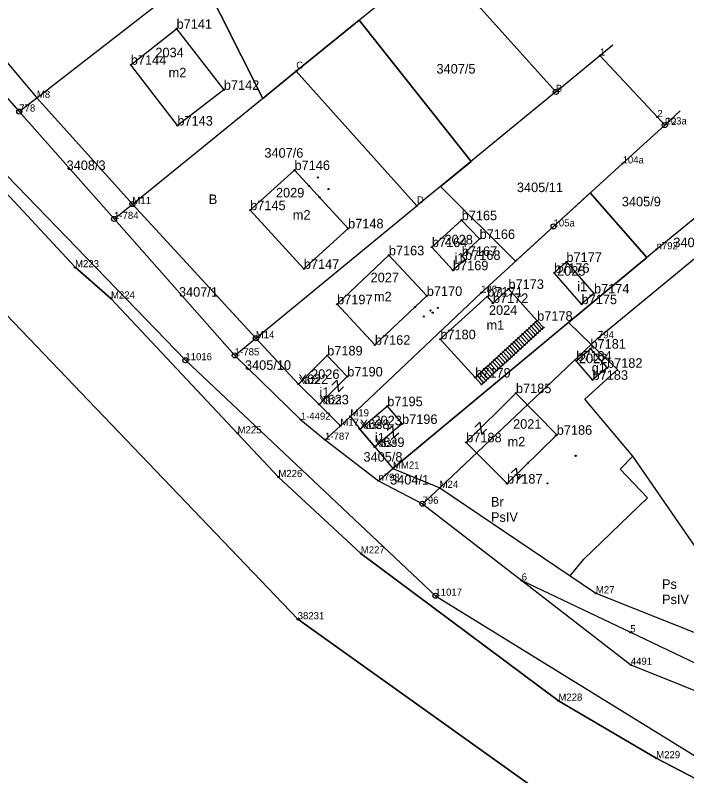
# Model space of a CAD drawing. Extents: x 7492083 to 7492670, y 5466693 to 5467065.
# Drawn here: x 7492234.2 to 7492339.8, y 5466813.8 to 5466933.4 of the extents above; entities that cross this region are included whole.
import ezdxf

# ---------------------------------------------------------------- set-up
doc = ezdxf.new("R2010")
doc.units = 0
for name, color, linetype in [('202-punkt graniczny', 7, 'Continuous'), ('202-punkt graniczny-Atr103', 7, 'Continuous'), ('203-punkt graniczny', 7, 'Continuous'), ('203-punkt graniczny-Atr103', 7, 'Continuous'), ('209-oznaczenie konturu klasyfikacyjnego', 7, 'Continuous'), ('210-oznaczenie konturu użytku gruntowego', 7, 'Continuous'), ('211-numer działki ewidencyjnej', 7, 'Continuous'), ('217-kontur klasyfikacyjny', 7, 'Continuous'), ('218-kontur użytku gruntowego', 7, 'Continuous'), ('219-działka ewidencyjna', 7, 'Continuous'), ('312-budynek ewidencyjny', 7, 'Continuous'), ('312-oznaczenie budynku ewidencyjnego', 7, 'Continuous'), ('312-oznaczenie budynku ewidencyjnego-Atr117', 7, 'Continuous'), ('352-schody', 7, 'Continuous'), ('991-Przehaczenie', 7, 'Continuous'), ('Punkt budynku', 7, 'Continuous'), ('Punkt budynku-Atr103', 7, 'Continuous')]:
    doc.layers.add(name, color=color, linetype=linetype)

# ---------------------------------------------------------------- blocks, each defined once
blk = doc.blocks.new('202')
blk.add_circle((0, 0), 0.4)
blk = doc.blocks.new('203')
blk.add_circle((0, 0), 0.09)
blk = doc.blocks.new('PUNKTBUD')
blk.add_circle((0, 0), 0.09)
blk = doc.blocks.new('991')
for p, q in [((-0.55, 0.75), (0.55, 0.75)), ((0.55, 0.75), (-0.55, -0.75)), ((-0.55, -0.75), (0.55, -0.75))]:
    blk.add_line(p, q)

msp = doc.modelspace()

# ---------------------------------------------------------------- linework, layer by layer
at = {"layer": '217-kontur klasyfikacyjny'}
for points in [[(7492263.09, 5466940.24), (7492273.09, 5466920.33)], [(7492278.38, 5466924.61), (7492288.26, 5466932.63)], [(7492288.26, 5466932.63), (7492305.89, 5466910.43)], [(7492273.09, 5466920.33), (7492278.38, 5466924.61)], [(7492305.89, 5466910.43), (7492301.07, 5466906.47)], [(7492301.07, 5466906.47), (7492312.89, 5466894.73)], [(7492318.86, 5466900.19), (7492324.64, 5466905.47)], [(7492324.64, 5466905.47), (7492333.55, 5466895.33)], [(7492312.89, 5466894.73), (7492318.86, 5466900.19)], [(7492333.55, 5466895.33), (7492321.19, 5466885.06)], [(7492321.19, 5466885.06), (7492293.59, 5466862.1)], [(7492324.8, 5466881.61), (7492321.19, 5466885.06)], [(7492328.91, 5466877.68), (7492324.8, 5466881.61)], [(7492323.78, 5466873.04), (7492328.91, 5466877.68)], [(7492331.33, 5466864.06), (7492323.78, 5466873.04)], [(7492329.32, 5466862.02), (7492331.33, 5466864.06)], [(7492341.15, 5466849.84), (7492331.33, 5466864.06)], [(7492293.59, 5466862.1), (7492300.94, 5466859.08)], [(7492333.65, 5466857.49), (7492329.32, 5466862.02)], [(7492300.94, 5466859.08), (7492321.46, 5466845.24)], [(7492323.63, 5466847.88), (7492333.65, 5466857.49)], [(7492321.46, 5466845.24), (7492323.63, 5466847.88)], [(7492321.46, 5466845.24), (7492325.52, 5466842.5)], [(7492325.52, 5466842.5), (7492392.56, 5466815.84)]]:
    msp.add_lwpolyline(points, dxfattribs=at)
at = {"layer": '218-kontur użytku gruntowego'}
for points in [[(7492273.09, 5466920.33), (7492263.09, 5466940.24)], [(7492223.67, 5466936.92), (7492237.56, 5466920.41)], [(7492288.26, 5466932.63), (7492278.38, 5466924.61)], [(7492305.89, 5466910.43), (7492288.26, 5466932.63)], [(7492278.38, 5466924.61), (7492273.09, 5466920.33)], [(7492237.56, 5466920.41), (7492252.59, 5466903.71)], [(7492243.57, 5466893.77), (7492219.52, 5466919.65)], [(7492278.6, 5466838.41), (7492203.36, 5466916.98)], [(7492301.07, 5466906.47), (7492305.89, 5466910.43)], [(7492312.89, 5466894.73), (7492301.07, 5466906.47)], [(7492324.64, 5466905.47), (7492318.86, 5466900.19)], [(7492333.55, 5466895.33), (7492324.64, 5466905.47)], [(7492252.59, 5466903.71), (7492272, 5466882.61)], [(7492318.86, 5466900.19), (7492312.89, 5466894.73)], [(7492321.19, 5466885.06), (7492333.55, 5466895.33)], [(7492249.22, 5466888.85), (7492243.57, 5466893.77)], [(7492269.15, 5466867.65), (7492249.22, 5466888.85)], [(7492321.19, 5466885.06), (7492293.59, 5466862.1)], [(7492324.8, 5466881.61), (7492321.19, 5466885.06)], [(7492272, 5466882.61), (7492278.71, 5466875.41)], [(7492328.91, 5466877.68), (7492324.8, 5466881.61)], [(7492323.78, 5466873.04), (7492328.91, 5466877.68)], [(7492278.71, 5466875.41), (7492281.96, 5466872.21)], [(7492331.33, 5466864.06), (7492323.78, 5466873.04)], [(7492281.96, 5466872.21), (7492285.31, 5466868.86)], [(7492285.31, 5466868.86), (7492286.89, 5466870.32)], [(7492286.89, 5466870.32), (7492288.36, 5466868.33)], [(7492275.56, 5466860.78), (7492269.15, 5466867.65)], [(7492288.36, 5466868.33), (7492290.72, 5466865.51)], [(7492290.72, 5466865.51), (7492293.59, 5466862.1)], [(7492329.32, 5466862.02), (7492331.33, 5466864.06)], [(7492341.15, 5466849.84), (7492331.33, 5466864.06)], [(7492293.59, 5466862.1), (7492300.94, 5466859.08)], [(7492333.65, 5466857.49), (7492329.32, 5466862.02)], [(7492288.53, 5466848.76), (7492275.56, 5466860.78)], [(7492300.94, 5466859.08), (7492321.46, 5466845.24)], [(7492323.63, 5466847.88), (7492333.65, 5466857.49)], [(7492319.62, 5466825.61), (7492288.53, 5466848.76)], [(7492321.46, 5466845.24), (7492323.63, 5466847.88)], [(7492321.46, 5466845.24), (7492325.52, 5466842.5)], [(7492325.52, 5466842.5), (7492392.56, 5466815.84)], [(7492330.31, 5466801.52), (7492278.6, 5466838.41)], [(7492335.01, 5466816.56), (7492319.62, 5466825.61)], [(7492351.02, 5466808.26), (7492335.01, 5466816.56)]]:
    msp.add_lwpolyline(points, dxfattribs=at)
at = {"layer": '219-działka ewidencyjna'}
for points in [[(7492237.56, 5466920.41), (7492278.95, 5466952.56)], [(7492198.51, 5466943.63), (7492260.93, 5466879.15)], [(7492300.32, 5466942.4), (7492278.38, 5466924.61)], [(7492300.32, 5466942.4), (7492319.2, 5466921.35)], [(7492223.67, 5466936.92), (7492237.56, 5466920.41)], [(7492220.55, 5466934.37), (7492234.8, 5466918.26)], [(7492326.15, 5466927.06), (7492328.2, 5466928.74)], [(7492319.2, 5466921.35), (7492326.15, 5466927.06)], [(7492326.15, 5466927.06), (7492335.19, 5466917.39)], [(7492252.59, 5466903.71), (7492278.38, 5466924.61)], [(7492278.38, 5466924.61), (7492297.36, 5466903.43)], [(7492319.2, 5466921.35), (7492297.36, 5466903.43)], [(7492234.8, 5466918.26), (7492237.56, 5466920.41)], [(7492237.56, 5466920.41), (7492252.59, 5466903.71)], [(7492219.52, 5466919.65), (7492243.57, 5466893.77)], [(7492234.8, 5466918.26), (7492249.71, 5466901.37)], [(7492336.47, 5466916.23), (7492338.8, 5466918.35)], [(7492203.36, 5466916.98), (7492278.6, 5466838.41)], [(7492335.19, 5466917.39), (7492336.36, 5466916.13)], [(7492329.72, 5466910.1), (7492336.36, 5466916.13)], [(7492336.36, 5466916.13), (7492336.47, 5466916.23)], [(7492318.86, 5466900.19), (7492329.72, 5466910.1)], [(7492335.07, 5466896.6), (7492349.18, 5466908.17)], [(7492325.85, 5466882.61), (7492352.68, 5466904.74)], [(7492249.71, 5466901.37), (7492252.59, 5466903.71)], [(7492252.59, 5466903.71), (7492272, 5466882.61)], [(7492272, 5466882.61), (7492297.36, 5466903.43)], [(7492249.71, 5466901.37), (7492268.71, 5466879.92)], [(7492307.46, 5466889.77), (7492318.86, 5466900.19)], [(7492293.59, 5466862.1), (7492335.07, 5466896.6)], [(7492243.57, 5466893.77), (7492249.22, 5466888.85)], [(7492286.89, 5466870.32), (7492307.46, 5466889.77)], [(7492249.22, 5466888.85), (7492269.15, 5466867.65)], [(7492268.71, 5466879.92), (7492272, 5466882.61)], [(7492272, 5466882.61), (7492278.71, 5466875.41)], [(7492300.94, 5466859.08), (7492325.85, 5466882.61)], [(7492268.71, 5466879.92), (7492279.09, 5466869.8)], [(7492260.93, 5466879.15), (7492300.27, 5466842.12)], [(7492278.71, 5466875.41), (7492281.96, 5466872.21)], [(7492281.96, 5466872.21), (7492285.31, 5466868.86)], [(7492285.31, 5466868.86), (7492286.89, 5466870.32)], [(7492286.89, 5466870.32), (7492288.36, 5466868.33)], [(7492279.09, 5466869.8), (7492282.91, 5466866.65)], [(7492282.91, 5466866.65), (7492285.31, 5466868.86)], [(7492269.15, 5466867.65), (7492275.56, 5466860.78)], [(7492288.36, 5466868.33), (7492290.72, 5466865.51)], [(7492282.91, 5466866.65), (7492291.31, 5466860.2)], [(7492290.72, 5466865.51), (7492293.59, 5466862.1)], [(7492291.31, 5466860.2), (7492293.59, 5466862.1)], [(7492293.59, 5466862.1), (7492300.94, 5466859.08)], [(7492275.56, 5466860.78), (7492288.53, 5466848.76)], [(7492291.31, 5466860.2), (7492298.24, 5466856.58)], [(7492298.24, 5466856.58), (7492300.94, 5466859.08)], [(7492300.94, 5466859.08), (7492325.52, 5466842.5)], [(7492298.24, 5466856.58), (7492313.85, 5466844.52)], [(7492288.53, 5466848.76), (7492319.62, 5466825.61)], [(7492313.85, 5466844.52), (7492331.01, 5466831.25)], [(7492313.85, 5466844.52), (7492330.94, 5466836.37)], [(7492325.52, 5466842.5), (7492408.22, 5466809.61)], [(7492300.27, 5466842.12), (7492349.95, 5466811.49)], [(7492278.6, 5466838.41), (7492330.31, 5466801.52)], [(7492330.94, 5466836.37), (7492355.23, 5466824.8)], [(7492331.01, 5466831.25), (7492370.62, 5466815.37)], [(7492319.62, 5466825.61), (7492335.01, 5466816.56)], [(7492335.01, 5466816.56), (7492351.02, 5466808.26)]]:
    msp.add_lwpolyline(points, dxfattribs=at)
at = {"layer": '312-budynek ewidencyjny'}
for points in [[(7492252.34, 5466925.62), (7492259.54, 5466931.27)], [(7492259.54, 5466931.27), (7492266.98, 5466921.67)], [(7492259.67, 5466916.06), (7492252.34, 5466925.62)], [(7492266.98, 5466921.67), (7492259.67, 5466916.06)], [(7492271.12, 5466902.75), (7492278.1, 5466909.06)], [(7492278.1, 5466909.06), (7492286.53, 5466899.89)], [(7492279.56, 5466893.52), (7492271.12, 5466902.75)], [(7492299.71, 5466896.95), (7492304.4, 5466901.17)], [(7492304.4, 5466901.17), (7492307.22, 5466898.23)], [(7492286.53, 5466899.89), (7492279.56, 5466893.52)], [(7492307.22, 5466898.23), (7492304.41, 5466895.55)], [(7492303.03, 5466893.3), (7492299.71, 5466896.95)], [(7492284.8, 5466887.95), (7492292.94, 5466895.65)], [(7492292.94, 5466895.65), (7492298.91, 5466889.26)], [(7492304.41, 5466895.55), (7492304.93, 5466894.93)], [(7492304.93, 5466894.93), (7492303.03, 5466893.3)], [(7492318.94, 5466892.91), (7492320.88, 5466894.6)], [(7492320.88, 5466894.6), (7492325.22, 5466889.66)], [(7492323.27, 5466887.97), (7492318.94, 5466892.91)], [(7492309.31, 5466888.15), (7492311.76, 5466890.36)], [(7492311.76, 5466890.36), (7492316.28, 5466885.36)], [(7492298.91, 5466889.26), (7492290.75, 5466881.58)], [(7492301.04, 5466882.45), (7492308.43, 5466889.16)], [(7492308.43, 5466889.16), (7492309.31, 5466888.15)], [(7492325.22, 5466889.66), (7492323.27, 5466887.97)], [(7492290.75, 5466881.58), (7492284.8, 5466887.95)], [(7492316.28, 5466885.36), (7492306.53, 5466876.43)], [(7492306.53, 5466876.43), (7492301.04, 5466882.45)], [(7492322.42, 5466879.08), (7492324.66, 5466880.97)], [(7492324.66, 5466880.97), (7492327.27, 5466877.96)], [(7492278.71, 5466875.41), (7492283.24, 5466879.9)], [(7492283.24, 5466879.9), (7492286.4, 5466876.6)], [(7492325, 5466876.07), (7492322.42, 5466879.08)], [(7492327.27, 5466877.96), (7492325, 5466876.07)], [(7492286.4, 5466876.6), (7492281.96, 5466872.21)], [(7492281.96, 5466872.21), (7492278.71, 5466875.41)], [(7492305.11, 5466866.24), (7492312.94, 5466873.98)], [(7492312.94, 5466873.98), (7492319.36, 5466867.43)], [(7492288.36, 5466868.33), (7492292.69, 5466871.92)], [(7492292.69, 5466871.92), (7492295.02, 5466869.13)], [(7492295.02, 5466869.13), (7492290.72, 5466865.51)], [(7492290.72, 5466865.51), (7492288.36, 5466868.33)], [(7492319.36, 5466867.43), (7492311.54, 5466859.75)], [(7492311.54, 5466859.75), (7492305.11, 5466866.24)]]:
    msp.add_lwpolyline(points, dxfattribs=at)
at = {"layer": '352-schody'}
for p, q in [((7492306.53, 5466876.43), (7492316.28, 5466885.36)), ((7492317.27, 5466884.28), (7492307.52, 5466875.35)), ((7492316, 5466883.12), (7492315.01, 5466884.2)), ((7492316.34, 5466883.43), (7492315.35, 5466884.51)), ((7492316.68, 5466883.74), (7492315.69, 5466884.82)), ((7492317.01, 5466884.05), (7492316.03, 5466885.13)), ((7492316.28, 5466885.36), (7492317.27, 5466884.28)), ((7492314.98, 5466882.19), (7492313.99, 5466883.27)), ((7492315.32, 5466882.5), (7492314.33, 5466883.58)), ((7492315.66, 5466882.81), (7492314.67, 5466883.89)), ((7492313.63, 5466880.94), (7492312.64, 5466882.02)), ((7492313.97, 5466881.25), (7492312.98, 5466882.33)), ((7492314.31, 5466881.56), (7492313.31, 5466882.64)), ((7492314.64, 5466881.88), (7492313.65, 5466882.95)), ((7492312.27, 5466879.7), (7492311.28, 5466880.78)), ((7492312.6, 5466880.01), (7492311.62, 5466881.09)), ((7492312.94, 5466880.32), (7492311.96, 5466881.4)), ((7492313.29, 5466880.63), (7492312.3, 5466881.71)), ((7492310.91, 5466878.46), (7492309.92, 5466879.54)), ((7492311.25, 5466878.77), (7492310.26, 5466879.85)), ((7492311.59, 5466879.08), (7492310.6, 5466880.16)), ((7492311.93, 5466879.39), (7492310.94, 5466880.47)), ((7492309.56, 5466877.21), (7492308.57, 5466878.29)), ((7492309.89, 5466877.52), (7492308.9, 5466878.6)), ((7492310.23, 5466877.84), (7492309.24, 5466878.92)), ((7492310.57, 5466878.15), (7492309.58, 5466879.23)), ((7492308.19, 5466875.97), (7492307.21, 5466877.05)), ((7492308.54, 5466876.28), (7492307.55, 5466877.36)), ((7492308.88, 5466876.59), (7492307.89, 5466877.67)), ((7492309.22, 5466876.9), (7492308.23, 5466877.98)), ((7492307.52, 5466875.35), (7492306.53, 5466876.43)), ((7492307.86, 5466875.66), (7492306.87, 5466876.74))]:
    msp.add_line(p, q, dxfattribs=at)

# ---------------------------------------------------------------- block references
at = {"layer": '202-punkt graniczny'}
for p in [(7492319.2, 5466921.35), (7492234.8, 5466918.26), (7492336.36, 5466916.13), (7492252.59, 5466903.71), (7492249.71, 5466901.37), (7492318.86, 5466900.19), (7492272, 5466882.61), (7492260.93, 5466879.15), (7492268.71, 5466879.92), (7492298.24, 5466856.58), (7492300.27, 5466842.12)]:
    msp.add_blockref('202', p, dxfattribs=at)
at = {"layer": '203-punkt graniczny'}
for p in [(7492326.15, 5466927.06), (7492278.38, 5466924.61), (7492237.56, 5466920.41), (7492335.19, 5466917.39), (7492336.47, 5466916.23), (7492329.72, 5466910.1), (7492297.36, 5466903.43), (7492335.07, 5466896.6), (7492243.57, 5466893.77), (7492307.46, 5466889.77), (7492249.22, 5466888.85), (7492325.85, 5466882.61), (7492278.71, 5466875.41), (7492281.96, 5466872.21), (7492279.09, 5466869.8), (7492286.89, 5466870.32), (7492285.31, 5466868.86), (7492269.15, 5466867.65), (7492288.36, 5466868.33), (7492282.91, 5466866.65), (7492290.72, 5466865.51), (7492293.59, 5466862.1), (7492275.56, 5466860.78), (7492291.31, 5466860.2), (7492300.94, 5466859.08), (7492288.53, 5466848.76), (7492313.85, 5466844.52), (7492325.52, 5466842.5), (7492278.6, 5466838.41), (7492330.94, 5466836.37), (7492331.01, 5466831.25), (7492319.62, 5466825.61), (7492335.01, 5466816.56)]:
    msp.add_blockref('203', p, dxfattribs=at)
at = {"layer": '991-Przehaczenie'}
for p, rotation in [((7492284.87, 5466875.09), 44.674), ((7492293.59, 5466867.93), 40.09), ((7492307.37, 5466868.47), 44.668), ((7492313.1, 5466861.28), 44.483999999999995)]:
    msp.add_blockref('991', p, dxfattribs=dict(at, rotation=rotation))
at = {"layer": 'Punkt budynku'}
for p in [(7492259.54, 5466931.27), (7492252.34, 5466925.62), (7492266.98, 5466921.67), (7492259.67, 5466916.06), (7492278.1, 5466909.06), (7492281.77, 5466907.89), (7492280.37, 5466906.59), (7492283.44, 5466906.07), (7492282.04, 5466904.78), (7492271.12, 5466902.75), (7492304.4, 5466901.17), (7492286.53, 5466899.89), (7492307.22, 5466898.23), (7492299.71, 5466896.95), (7492292.94, 5466895.65), (7492304.41, 5466895.55), (7492304.93, 5466894.93), (7492320.88, 5466894.6), (7492279.56, 5466893.52), (7492303.03, 5466893.3), (7492318.94, 5466892.91), (7492311.76, 5466890.36), (7492298.91, 5466889.26), (7492308.43, 5466889.16), (7492325.22, 5466889.66), (7492284.8, 5466887.95), (7492309.31, 5466888.15), (7492323.27, 5466887.97), (7492297.05, 5466887.51), (7492299.49, 5466886.98), (7492299.83, 5466886.63), (7492300.65, 5466887.4), (7492298.46, 5466886.02), (7492316.28, 5466885.36), (7492315.01, 5466884.2), (7492315.35, 5466884.51), (7492315.69, 5466884.82), (7492316.03, 5466885.13), (7492317.27, 5466884.28), (7492313.65, 5466882.95), (7492313.99, 5466883.27), (7492314.33, 5466883.58), (7492314.67, 5466883.89), (7492316, 5466883.12), (7492316.34, 5466883.43), (7492316.68, 5466883.74), (7492317.01, 5466884.05), (7492301.04, 5466882.45), (7492312.64, 5466882.02), (7492312.98, 5466882.33), (7492313.31, 5466882.64), (7492314.64, 5466881.88), (7492314.98, 5466882.19), (7492315.32, 5466882.5), (7492315.66, 5466882.81), (7492290.75, 5466881.58), (7492311.28, 5466880.78), (7492311.62, 5466881.09), (7492311.96, 5466881.4), (7492312.3, 5466881.71), (7492313.29, 5466880.63), (7492313.63, 5466880.94), (7492313.97, 5466881.25), (7492314.31, 5466881.56), (7492324.66, 5466880.97), (7492283.24, 5466879.9), (7492309.92, 5466879.54), (7492310.26, 5466879.85), (7492310.6, 5466880.16), (7492310.94, 5466880.47), (7492311.93, 5466879.39), (7492312.27, 5466879.7), (7492312.6, 5466880.01), (7492312.94, 5466880.32), (7492308.57, 5466878.29), (7492308.9, 5466878.6), (7492309.24, 5466878.92), (7492309.58, 5466879.23), (7492310.57, 5466878.15), (7492310.91, 5466878.46), (7492311.25, 5466878.77), (7492311.59, 5466879.08), (7492322.42, 5466879.08), (7492307.21, 5466877.05), (7492307.55, 5466877.36), (7492307.89, 5466877.67), (7492308.23, 5466877.98), (7492309.56, 5466877.21), (7492309.89, 5466877.52), (7492310.23, 5466877.84), (7492327.27, 5466877.96), (7492286.4, 5466876.6), (7492306.53, 5466876.43), (7492306.87, 5466876.74), (7492308.19, 5466875.97), (7492308.54, 5466876.28), (7492308.88, 5466876.59), (7492309.22, 5466876.9), (7492325, 5466876.07), (7492278.71, 5466875.41), (7492307.52, 5466875.35), (7492307.86, 5466875.66), (7492312.94, 5466873.98), (7492281.96, 5466872.21), (7492292.69, 5466871.92), (7492295.02, 5466869.13), (7492288.36, 5466868.33), (7492319.36, 5466867.43), (7492305.11, 5466866.24), (7492319.22, 5466867.29), (7492290.72, 5466865.51), (7492322.33, 5466864.11), (7492314.8, 5466862.95), (7492311.54, 5466859.75), (7492317.92, 5466859.78)]:
    msp.add_blockref('PUNKTBUD', p, dxfattribs=at)

# ---------------------------------------------------------------- texts
at = {"layer": '202-punkt graniczny-Atr103'}
for s, height, p in [('B', 1.12, (7492319.2, 5466921.35)), ('778', 1.125, (7492234.8, 5466918.26)), ('P2', 1.125, (7492336.36, 5466916.13)), ('M11', 1.125, (7492252.59, 5466903.71)), ('1-784', 1.125, (7492249.71, 5466901.37)), ('105a', 1.125, (7492318.86, 5466900.19)), ('M14', 1.125, (7492272, 5466882.61)), ('1-785', 1.125, (7492268.71, 5466879.92)), ('11016', 1.125, (7492260.93, 5466879.15)), ('796', 1.125, (7492298.24, 5466856.58)), ('11017', 1.125, (7492300.27, 5466842.12))]:
    msp.add_text(s, height=height, dxfattribs=at).set_placement(p)
at = {"layer": '203-punkt graniczny-Atr103'}
for s, height, p in [('1', 1.12, (7492326.15, 5466927.06)), ('C', 1.12, (7492278.38, 5466924.99)), ('M8', 1.125, (7492237.56, 5466920.41)), ('2', 1.12, (7492335.19, 5466917.39)), ('103a', 1.125, (7492336.47, 5466916.23)), ('104a', 1.125, (7492329.72, 5466910.1)), ('D', 1.12, (7492297.36, 5466903.81)), ('n792', 1.125, (7492335.07, 5466896.6)), ('M223', 1.125, (7492243.57, 5466893.77)), ('106a', 1.125, (7492307.46, 5466889.77)), ('M224', 1.125, (7492249.22, 5466888.85)), ('794', 1.125, (7492325.85, 5466882.61)), ('X622', 1.125, (7492278.71, 5466875.41)), ('X623', 1.125, (7492281.96, 5466872.21)), ('M19', 1.125, (7492286.89, 5466870.32)), ('1-4492', 1.125, (7492279.09, 5466869.8)), ('M17', 1.125, (7492285.31, 5466868.86)), ('M225', 1.125, (7492269.15, 5466867.65)), ('X638', 1.125, (7492288.36, 5466868.33)), ('1-787', 1.125, (7492282.91, 5466866.65)), ('X639', 1.125, (7492290.72, 5466865.51)), ('MM21', 1.125, (7492293.59, 5466862.1)), ('M226', 1.125, (7492275.56, 5466860.78)), ('n793', 1.125, (7492291.31, 5466860.2)), ('M24', 1.125, (7492300.94, 5466859.08)), ('M227', 1.125, (7492288.53, 5466848.76)), ('6', 1.12, (7492313.85, 5466844.52)), ('M27', 1.125, (7492325.52, 5466842.5)), ('38231', 1.125, (7492278.6, 5466838.41)), ('5', 1.12, (7492330.94, 5466836.37)), ('4491', 1.125, (7492331.01, 5466831.25)), ('M228', 1.125, (7492319.62, 5466825.61)), ('M229', 1.125, (7492335.01, 5466816.56))]:
    msp.add_text(s, height=height, dxfattribs=at).set_placement(p)
at = {"layer": '209-oznaczenie konturu klasyfikacyjnego'}
for p in [(7492309.01, 5466853.74), (7492335.92, 5466840.8)]:
    msp.add_text('PsIV', height=1.5, dxfattribs=at).set_placement(p)
at = {"layer": '210-oznaczenie konturu użytku gruntowego'}
for s, p in [('B', (7492264.61, 5466903.72)), ('Br', (7492309.01, 5466856.14)), ('Ps', (7492335.92, 5466843.2))]:
    msp.add_text(s, height=1.5, dxfattribs=at).set_placement(p)
at = {"layer": '211-numer działki ewidencyjnej'}
for s, p in [('3407/5', (7492300.44, 5466924.23)), ('3407/6', (7492273.36, 5466911.01)), ('3408/3', (7492242.24, 5466909.06)), ('3405/11', (7492313.09, 5466905.59)), ('3405/9', (7492329.6, 5466903.35)), ('3404/2', (7492337.71, 5466896.93)), ('3407/1', (7492259.92, 5466889.14)), ('3405/10', (7492270.3, 5466877.64)), ('3405/8', (7492288.95, 5466863.2)), ('3404/1', (7492293.14, 5466859.6))]:
    msp.add_text(s, height=1.5, dxfattribs=at).set_placement(p)
at = {"layer": '312-oznaczenie budynku ewidencyjnego'}
for s, p in [('2034', (7492256.21, 5466926.79)), ('2029', (7492275.18, 5466904.75)), ('2028', (7492301.7, 5466897.38)), ('2025', (7492319.41, 5466892.44)), ('2027', (7492290.07, 5466891.42)), ('2024', (7492308.69, 5466886.29)), ('2022', (7492322.86, 5466878.69)), ('2026', (7492280.71, 5466876.22)), ('2023', (7492290.52, 5466868.93)), ('2021', (7492312.49, 5466868.37))]:
    msp.add_text(s, height=1.5, dxfattribs=at).set_placement(p)
at = {"layer": '312-oznaczenie budynku ewidencyjnego-Atr117'}
for s, p in [('m2', (7492258.29, 5466923.65)), ('m2', (7492277.83, 5466901.26)), ('i1', (7492303.28, 5466894.5)), ('i1', (7492322.58, 5466890.01)), ('m2', (7492290.6, 5466888.42)), ('m1', (7492308.31, 5466883.94)), ('g1', (7492324.86, 5466877.22)), ('i1', (7492282.03, 5466873.37)), ('i1', (7492290.76, 5466866.23)), ('m2', (7492311.62, 5466865.6))]:
    msp.add_text(s, height=1.5, dxfattribs=at).set_placement(p)
at = {"layer": 'Punkt budynku-Atr103'}
for s, p in [('b7141', (7492259.54, 5466931.27)), ('b7144', (7492252.34, 5466925.62)), ('b7142', (7492266.98, 5466921.67)), ('b7143', (7492259.67, 5466916.06)), ('b7146', (7492278.1, 5466909.06)), ('b7145', (7492271.12, 5466902.75)), ('b7165', (7492304.4, 5466901.17)), ('b7148', (7492286.53, 5466899.89)), ('b7166', (7492307.22, 5466898.23)), ('b7164', (7492299.71, 5466896.95)), ('b7163', (7492292.94, 5466895.65)), ('b7167', (7492304.41, 5466895.55)), ('b7168', (7492304.93, 5466894.93)), ('b7177', (7492320.88, 5466894.6)), ('b7147', (7492279.56, 5466893.52)), ('b7169', (7492303.03, 5466893.3)), ('b7176', (7492318.94, 5466892.91)), ('b7173', (7492311.76, 5466890.36)), ('b7170', (7492298.91, 5466889.26)), ('b7171', (7492308.43, 5466889.16)), ('b7174', (7492325.22, 5466889.66)), ('b7197', (7492284.8, 5466887.95)), ('b7172', (7492309.31, 5466888.15)), ('b7175', (7492323.27, 5466887.97)), ('b7178', (7492316.28, 5466885.36)), ('b7162', (7492290.75, 5466881.58)), ('b7180', (7492301.04, 5466882.45)), ('b7181', (7492324.66, 5466880.97)), ('b7189', (7492283.24, 5466879.9)), ('b7184', (7492322.42, 5466879.08)), ('b7182', (7492327.27, 5466877.96)), ('b7190', (7492286.4, 5466876.6)), ('b7179', (7492306.53, 5466876.43)), ('b7183', (7492325, 5466876.07)), ('X622', (7492278.71, 5466875.41)), ('b7185', (7492312.94, 5466873.98)), ('X623', (7492281.96, 5466872.21)), ('b7195', (7492292.69, 5466871.92)), ('X638', (7492288.36, 5466868.33)), ('b7196', (7492295.02, 5466869.13)), ('b7186', (7492319.36, 5466867.43)), ('b7188', (7492305.11, 5466866.24)), ('X639', (7492290.72, 5466865.51)), ('b7187', (7492311.54, 5466859.75))]:
    msp.add_text(s, height=1.5, dxfattribs=at).set_placement(p)

doc.saveas('drawing.dxf')
